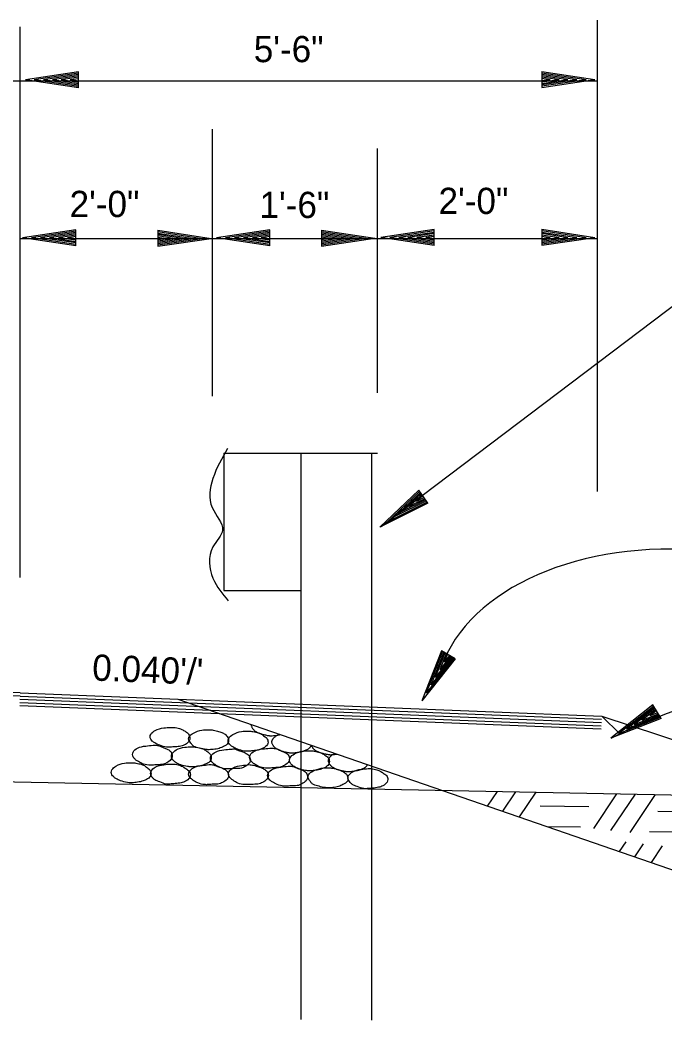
# Model space of a CAD drawing. Extents: x 1931522 to 1935523, y 600380 to 605075.
# Drawn here: x 1933348.9 to 1933498.3, y 604722.8 to 604954.5 of the extents above; entities that cross this region are included whole.
import ezdxf

# ---------------------------------------------------------------- set-up
doc = ezdxf.new("R2010")
doc.units = 0
doc.layers.add('Default', color=7, linetype='Continuous')
doc.layers.add('R_Border', color=7, linetype='Continuous')

msp = doc.modelspace()

# ---------------------------------------------------------------- linework, layer by layer
at = {"layer": 'Default'}
for p, q in [((1933482.65, 604845.22), (1933482.65, 604954.46)), ((1933348.95, 604825.33), (1933348.95, 604952.88)), ((1933152.12, 604940.38), (1933482.65, 604940.38)), ((1933362.48, 604942.45), (1933350.16, 604940.6)), ((1933362.48, 604938.73), (1933350.16, 604940.6)), ((1933362.48, 604942.13), (1933352.22, 604940.6)), ((1933362.48, 604939.05), (1933352.22, 604940.6)), ((1933362.48, 604941.81), (1933354.34, 604940.6)), ((1933362.48, 604939.37), (1933354.34, 604940.6)), ((1933362.48, 604941.51), (1933356.41, 604940.6)), ((1933362.48, 604939.67), (1933356.41, 604940.6)), ((1933362.48, 604941.19), (1933358.47, 604940.6)), ((1933362.48, 604939.99), (1933358.47, 604940.6)), ((1933362.48, 604940.87), (1933360.54, 604940.6)), ((1933362.48, 604940.31), (1933360.54, 604940.6)), ((1933362.48, 604938.73), (1933362.48, 604942.45)), ((1933469.71, 604942.57), (1933482.03, 604940.7)), ((1933469.71, 604942.57), (1933469.71, 604938.86)), ((1933469.71, 604942.25), (1933479.97, 604940.7)), ((1933469.71, 604941.93), (1933477.85, 604940.7)), ((1933469.71, 604941.64), (1933475.78, 604940.7)), ((1933469.71, 604941.32), (1933473.72, 604940.7)), ((1933469.71, 604941), (1933471.65, 604940.7)), ((1933469.71, 604938.86), (1933482.03, 604940.7)), ((1933469.71, 604940.11), (1933473.72, 604940.7)), ((1933469.71, 604939.5), (1933477.85, 604940.7)), ((1933469.71, 604939.18), (1933479.97, 604940.7)), ((1933469.71, 604939.79), (1933475.78, 604940.7)), ((1933469.71, 604940.43), (1933471.65, 604940.7)), ((1933393.51, 604867.32), (1933393.51, 604929.19)), ((1933431.72, 604868.12), (1933431.72, 604924.68)), ((1933361.82, 604905.89), (1933349.49, 604904.04)), ((1933361.82, 604905.57), (1933351.56, 604904.04)), ((1933361.82, 604902.17), (1933361.82, 604905.89)), ((1933380.84, 604905.76), (1933393.16, 604903.89)), ((1933380.84, 604905.76), (1933380.84, 604902.05)), ((1933406.72, 604905.89), (1933394.39, 604904.04)), ((1933406.72, 604905.57), (1933396.46, 604904.04)), ((1933406.72, 604902.17), (1933406.72, 604905.89)), ((1933418.7, 604905.79), (1933431.03, 604903.92)), ((1933418.7, 604905.79), (1933418.7, 604902.07)), ((1933444.81, 604905.91), (1933432.48, 604904.07)), ((1933444.81, 604905.59), (1933434.55, 604904.07)), ((1933444.81, 604902.2), (1933444.81, 604905.91)), ((1933469.71, 604905.99), (1933482.03, 604904.12)), ((1933469.71, 604905.99), (1933469.71, 604902.27)), ((1933469.71, 604905.67), (1933479.97, 604904.12)), ((1933348.95, 604903.82), (1933482.65, 604903.82)), ((1933361.82, 604902.17), (1933349.49, 604904.04)), ((1933361.82, 604902.49), (1933351.56, 604904.04)), ((1933361.82, 604905.25), (1933353.68, 604904.04)), ((1933361.82, 604902.81), (1933353.68, 604904.04)), ((1933361.82, 604904.95), (1933355.74, 604904.04)), ((1933361.82, 604903.11), (1933355.74, 604904.04)), ((1933361.82, 604904.63), (1933357.81, 604904.04)), ((1933361.82, 604903.43), (1933357.81, 604904.04)), ((1933361.82, 604904.31), (1933359.88, 604904.04)), ((1933361.82, 604903.75), (1933359.88, 604904.04)), ((1933380.84, 604905.44), (1933391.1, 604903.89)), ((1933380.84, 604905.12), (1933388.98, 604903.89)), ((1933380.84, 604904.83), (1933386.92, 604903.89)), ((1933380.84, 604904.51), (1933384.85, 604903.89)), ((1933380.84, 604904.19), (1933382.78, 604903.89)), ((1933380.84, 604902.05), (1933393.16, 604903.89)), ((1933380.84, 604903.3), (1933384.85, 604903.89)), ((1933380.84, 604902.69), (1933388.98, 604903.89)), ((1933380.84, 604902.37), (1933391.1, 604903.89)), ((1933380.84, 604902.98), (1933386.92, 604903.89)), ((1933380.84, 604903.62), (1933382.78, 604903.89)), ((1933406.72, 604902.17), (1933394.39, 604904.04)), ((1933406.72, 604902.49), (1933396.46, 604904.04)), ((1933406.72, 604905.25), (1933398.58, 604904.04)), ((1933406.72, 604902.81), (1933398.58, 604904.04)), ((1933406.72, 604904.95), (1933400.64, 604904.04)), ((1933406.72, 604903.11), (1933400.64, 604904.04)), ((1933406.72, 604904.63), (1933402.71, 604904.04)), ((1933406.72, 604903.43), (1933402.71, 604904.04)), ((1933406.72, 604904.31), (1933404.78, 604904.04)), ((1933406.72, 604903.75), (1933404.78, 604904.04)), ((1933418.7, 604905.47), (1933428.96, 604903.92)), ((1933418.7, 604905.15), (1933426.85, 604903.92)), ((1933418.7, 604904.85), (1933424.78, 604903.92)), ((1933418.7, 604904.53), (1933422.71, 604903.92)), ((1933418.7, 604904.21), (1933420.65, 604903.92)), ((1933418.7, 604902.07), (1933431.03, 604903.92)), ((1933418.7, 604903.33), (1933422.71, 604903.92)), ((1933418.7, 604902.71), (1933426.85, 604903.92)), ((1933418.7, 604902.39), (1933428.96, 604903.92)), ((1933418.7, 604903.01), (1933424.78, 604903.92)), ((1933418.7, 604903.65), (1933420.65, 604903.92)), ((1933444.81, 604902.2), (1933432.48, 604904.07)), ((1933444.81, 604902.52), (1933434.55, 604904.07)), ((1933444.81, 604905.27), (1933436.66, 604904.07)), ((1933444.81, 604902.84), (1933436.66, 604904.07)), ((1933444.81, 604904.98), (1933438.73, 604904.07)), ((1933444.81, 604903.13), (1933438.73, 604904.07)), ((1933444.81, 604904.66), (1933440.8, 604904.07)), ((1933444.81, 604903.45), (1933440.8, 604904.07)), ((1933444.81, 604904.34), (1933442.86, 604904.07)), ((1933444.81, 604903.77), (1933442.86, 604904.07)), ((1933469.71, 604905.35), (1933477.85, 604904.12)), ((1933469.71, 604905.05), (1933475.78, 604904.12)), ((1933469.71, 604904.73), (1933473.72, 604904.12)), ((1933469.71, 604904.41), (1933471.65, 604904.12)), ((1933469.71, 604902.27), (1933482.03, 604904.12)), ((1933469.71, 604903.52), (1933473.72, 604904.12)), ((1933469.71, 604902.91), (1933477.85, 604904.12)), ((1933469.71, 604902.59), (1933479.97, 604904.12)), ((1933469.71, 604903.2), (1933475.78, 604904.12)), ((1933469.71, 604903.84), (1933471.65, 604904.12)), ((1933432.53, 604837.14), (1933501.84, 604889.53)), ((1933396.07, 604854.15), (1933396.07, 604822.31)), ((1933396.07, 604854.15), (1933431.72, 604854.15)), ((1933413.91, 604854.15), (1933413.91, 604722.96)), ((1933430.29, 604854), (1933430.29, 604722.83)), ((1933441.27, 604845.56), (1933432.21, 604837)), ((1933441.47, 604845.32), (1933433.89, 604838.16)), ((1933443.36, 604842.56), (1933441.27, 604845.56)), ((1933441.67, 604845.03), (1933435.69, 604839.43)), ((1933443, 604843.06), (1933435.69, 604839.43)), ((1933441.79, 604844.77), (1933437.35, 604840.59)), ((1933442.82, 604843.32), (1933437.35, 604840.59)), ((1933441.98, 604844.56), (1933439.03, 604841.77)), ((1933442.63, 604843.59), (1933439.03, 604841.77)), ((1933442.15, 604844.29), (1933440.73, 604842.96)), ((1933442.5, 604843.87), (1933440.73, 604842.96)), ((1933443.36, 604842.56), (1933432.21, 604837)), ((1933443.22, 604842.79), (1933433.89, 604838.16)), ((1933396.07, 604822.31), (1933413.91, 604822.31)), ((1933446.51, 604808.38), (1933441.93, 604796.77)), ((1933449.7, 604806.51), (1933446.51, 604808.38)), ((1933449.7, 604806.51), (1933441.93, 604796.77)), ((1933446.75, 604808.19), (1933442.96, 604798.57)), ((1933449.46, 604806.68), (1933442.96, 604798.57)), ((1933447.05, 604808.04), (1933444.02, 604800.41)), ((1933449.14, 604806.81), (1933444.02, 604800.41)), ((1933447.29, 604807.89), (1933445.03, 604802.16)), ((1933448.89, 604806.98), (1933445.03, 604802.16)), ((1933447.59, 604807.74), (1933446.09, 604803.98)), ((1933448.62, 604807.13), (1933446.09, 604803.98)), ((1933447.88, 604807.57), (1933447.15, 604805.75)), ((1933448.35, 604807.3), (1933447.15, 604805.75)), ((1933348.95, 604798.61), (1933201.33, 604804.52)), ((1933348.95, 604797.88), (1933201.33, 604803.78)), ((1933348.89, 604797.14), (1933483.54, 604791.75)), ((1933348.91, 604797.88), (1933483.57, 604792.49)), ((1933348.95, 604798.61), (1933483.61, 604793.23)), ((1933385.48, 604797.15), (1933446.72, 604776.01)), ((1933348.83, 604795.66), (1933483.48, 604790.27)), ((1933348.85, 604796.4), (1933483.51, 604791.01)), ((1933495.47, 604795.86), (1933485.72, 604788.08)), ((1933495.64, 604795.56), (1933487.52, 604789.09)), ((1933495.79, 604795.29), (1933489.34, 604790.18)), ((1933495.93, 604795.05), (1933491.11, 604791.21)), ((1933496.08, 604794.75), (1933492.91, 604792.24)), ((1933496.25, 604794.48), (1933494.73, 604793.28)), ((1933497.34, 604792.64), (1933495.47, 604795.86)), ((1933483.61, 604793.23), (1933664.23, 604733.18)), ((1933483.61, 604793.23), (1933487.84, 604789.02)), ((1933497.34, 604792.64), (1933485.72, 604788.08)), ((1933497.16, 604792.91), (1933487.52, 604789.09)), ((1933496.99, 604793.18), (1933489.34, 604790.18)), ((1933496.84, 604793.42), (1933491.11, 604791.21)), ((1933496.7, 604793.69), (1933492.91, 604792.24)), ((1933496.55, 604793.99), (1933494.73, 604793.28)), ((1933147.68, 604781.96), (1933541.06, 604774.13)), ((1933446.72, 604776.01), (1933570.77, 604733.18))]:
    msp.add_line(p, q, dxfattribs=at)
msp.add_arc((1933541.23, 604679.75), 121.72, 64.8876, 117.1378, dxfattribs=at)
msp.add_ellipse((1933505.82, 604791.35), major_axis=(-60.8, 7.42), ratio=0.655798, start_param=4.712389, end_param=6.093533, dxfattribs=at)
for points in [[(1933396.93, 604855.18), (1933393.58, 604848.26), (1933393.41, 604841.52), (1933395.82, 604836.33), (1933393.58, 604832.4), (1933393.58, 604825.14), (1933397.13, 604819.9)], [(1933383.82, 604790.6), (1933382.19, 604790.5), (1933380.22, 604789.91), (1933379.19, 604788.98), (1933379.04, 604788.44), (1933379.53, 604787.45), (1933380.12, 604787.01), (1933381.26, 604786.47), (1933382.83, 604786.03), (1933383.67, 604786.03), (1933384.85, 604786.12), (1933386.18, 604786.27), (1933387.21, 604786.67), (1933388.1, 604787.5), (1933388.24, 604788.14), (1933387.95, 604789.03), (1933387.31, 604789.62), (1933386.62, 604790.01), (1933385.54, 604790.45), (1933384.85, 604790.6), (1933383.82, 604790.6)], [(1933392.63, 604790.08), (1933391.01, 604789.98), (1933389.09, 604789.29), (1933388.1, 604788.5), (1933387.96, 604787.96), (1933388.5, 604786.93), (1933388.94, 604786.39), (1933390.12, 604785.89), (1933391.6, 604785.55), (1933392.43, 604785.45), (1933393.66, 604785.5), (1933395.04, 604785.75), (1933396.03, 604786.19), (1933397.06, 604786.98), (1933397.21, 604787.62), (1933396.91, 604788.5), (1933396.17, 604789.14), (1933395.44, 604789.49), (1933394.35, 604789.83), (1933393.66, 604789.98), (1933392.63, 604790.08)], [(1933401.81, 604789.71), (1933400.18, 604789.66), (1933398.22, 604788.97), (1933397.23, 604788.08), (1933397.08, 604787.49), (1933397.63, 604786.51), (1933398.17, 604786.07), (1933399.25, 604785.57), (1933400.82, 604785.13), (1933401.66, 604785.08), (1933402.84, 604785.18), (1933404.17, 604785.43), (1933405.2, 604785.82), (1933406.19, 604786.61), (1933406.34, 604787.2), (1933406.04, 604788.08), (1933405.3, 604788.67), (1933404.61, 604789.17), (1933403.53, 604789.51), (1933402.84, 604789.66), (1933401.81, 604789.71)], [(1933402.43, 604791.3), (1933402.43, 604791.27), (1933402.42, 604791.2), (1933402.43, 604791.13), (1933402.51, 604790.87), (1933402.62, 604790.6), (1933402.78, 604790.35), (1933402.87, 604790.22), (1933402.97, 604790.1), (1933403.23, 604789.85), (1933403.52, 604789.66), (1933403.78, 604789.51), (1933404.05, 604789.38), (1933404.32, 604789.27), (1933404.6, 604789.17), (1933405.38, 604788.95), (1933406.17, 604788.77), (1933406.59, 604788.7), (1933406.8, 604788.68), (1933407.01, 604788.67), (1933407.6, 604788.7), (1933407.89, 604788.73), (1933408.19, 604788.77), (1933408.71, 604788.85), (1933409.23, 604788.95)], [(1933409.09, 604789), (1933408.79, 604788.88), (1933408.55, 604788.77), (1933408.31, 604788.65), (1933408.01, 604788.47), (1933407.76, 604788.25), (1933407.53, 604788), (1933407.43, 604787.86), (1933407.32, 604787.71), (1933407.25, 604787.58), (1933407.19, 604787.44), (1933407.17, 604787.31), (1933407.17, 604787.24), (1933407.17, 604787.17), (1933407.25, 604786.9), (1933407.36, 604786.64), (1933407.52, 604786.38), (1933407.61, 604786.26), (1933407.72, 604786.14), (1933407.97, 604785.89), (1933408.26, 604785.7), (1933408.52, 604785.55), (1933408.79, 604785.42), (1933409.06, 604785.3), (1933409.34, 604785.2), (1933410.12, 604784.98), (1933410.91, 604784.81), (1933411.75, 604784.71), (1933411.9, 604784.71), (1933412.05, 604784.72), (1933412.34, 604784.74), (1933412.93, 604784.81), (1933413.27, 604784.86), (1933413.6, 604784.92), (1933413.93, 604784.98), (1933414.26, 604785.06), (1933414.53, 604785.13), (1933414.78, 604785.22), (1933415.04, 604785.33), (1933415.29, 604785.45), (1933415.57, 604785.6), (1933415.83, 604785.77), (1933416.06, 604785.97), (1933416.17, 604786.1), (1933416.28, 604786.24), (1933416.35, 604786.36), (1933416.39, 604786.48)], [(1933379.74, 604786.49), (1933378.02, 604786.3), (1933376.1, 604785.8), (1933375.11, 604784.87), (1933374.97, 604784.33), (1933375.46, 604783.29), (1933376.05, 604782.85), (1933377.13, 604782.26), (1933378.71, 604781.87), (1933379.49, 604781.87), (1933380.72, 604781.97), (1933382.1, 604782.06), (1933383.13, 604782.56), (1933384.02, 604783.39), (1933384.17, 604784.03), (1933383.87, 604784.92), (1933383.13, 604785.51), (1933382.45, 604785.8), (1933381.36, 604786.25), (1933380.72, 604786.44), (1933379.74, 604786.49)], [(1933388.67, 604786.07), (1933387.05, 604786.03), (1933385.08, 604785.39), (1933384.09, 604784.45), (1933383.95, 604783.91), (1933384.49, 604782.88), (1933385.03, 604782.43), (1933386.11, 604781.94), (1933387.69, 604781.55), (1933388.52, 604781.45), (1933389.7, 604781.55), (1933391.03, 604781.79), (1933392.07, 604782.19), (1933393.05, 604782.97), (1933393.2, 604783.61), (1933392.9, 604784.5), (1933392.16, 604785.09), (1933391.48, 604785.53), (1933390.39, 604785.88), (1933389.7, 604786.03), (1933388.67, 604786.07)], [(1933397.77, 604785.57), (1933396.14, 604785.43), (1933394.17, 604784.89), (1933393.14, 604783.95), (1933392.99, 604783.41), (1933393.53, 604782.43), (1933394.07, 604781.98), (1933395.21, 604781.34), (1933396.73, 604781), (1933397.57, 604781), (1933398.75, 604781.1), (1933400.18, 604781.15), (1933401.16, 604781.64), (1933402.1, 604782.47), (1933402.24, 604783.11), (1933401.95, 604784), (1933401.26, 604784.59), (1933400.52, 604784.93), (1933399.49, 604785.28), (1933398.8, 604785.57), (1933397.77, 604785.57)], [(1933406.72, 604785.8), (1933405.1, 604785.61), (1933403.18, 604785.12), (1933402.19, 604784.18), (1933402.05, 604783.64), (1933402.59, 604782.61), (1933403.13, 604782.16), (1933404.21, 604781.57), (1933405.79, 604781.18), (1933406.57, 604781.18), (1933407.8, 604781.28), (1933409.13, 604781.38), (1933410.21, 604781.87), (1933411.15, 604782.7), (1933411.3, 604783.34), (1933411, 604784.23), (1933410.26, 604784.82), (1933409.53, 604785.12), (1933408.49, 604785.61), (1933407.75, 604785.75), (1933406.72, 604785.8)], [(1933416.02, 604785.16), (1933414.4, 604785.12), (1933412.43, 604784.48), (1933411.45, 604783.54), (1933411.3, 604783), (1933411.84, 604781.97), (1933412.38, 604781.52), (1933413.46, 604781.03), (1933415.04, 604780.64), (1933415.87, 604780.54), (1933417.05, 604780.64), (1933418.38, 604780.88), (1933419.42, 604781.28), (1933420.4, 604782.06), (1933420.55, 604782.7), (1933420.25, 604783.59), (1933419.52, 604784.18), (1933418.83, 604784.62), (1933417.74, 604784.97), (1933417.05, 604785.12), (1933416.02, 604785.16)], [(1933416.34, 604786.5), (1933416.43, 604786.29), (1933416.53, 604786.09), (1933416.67, 604785.9), (1933416.82, 604785.71), (1933417.07, 604785.46), (1933417.36, 604785.27), (1933417.62, 604785.13), (1933417.89, 604784.99), (1933418.16, 604784.88), (1933418.44, 604784.78), (1933419.22, 604784.56), (1933420.02, 604784.38), (1933420.43, 604784.32), (1933420.64, 604784.29), (1933420.85, 604784.29), (1933421.44, 604784.31), (1933422.03, 604784.38), (1933422.34, 604784.43)], [(1933421.92, 604784.57), (1933421.66, 604784.45), (1933421.52, 604784.39), (1933421.39, 604784.32), (1933421.1, 604784.14), (1933420.85, 604783.92), (1933420.62, 604783.67), (1933420.51, 604783.53), (1933420.41, 604783.38), (1933420.33, 604783.25), (1933420.28, 604783.11), (1933420.25, 604782.98), (1933420.25, 604782.91), (1933420.26, 604782.84), (1933420.33, 604782.57), (1933420.45, 604782.31), (1933420.61, 604782.05), (1933420.7, 604781.93), (1933420.8, 604781.81), (1933421.06, 604781.56), (1933421.34, 604781.37), (1933421.61, 604781.22), (1933421.87, 604781.09), (1933422.15, 604780.97), (1933422.43, 604780.87), (1933423.21, 604780.65), (1933424, 604780.48), (1933424.84, 604780.38), (1933424.98, 604780.38), (1933425.13, 604780.39), (1933425.43, 604780.41), (1933426.02, 604780.48), (1933426.35, 604780.53), (1933426.69, 604780.59), (1933427.02, 604780.65), (1933427.35, 604780.73), (1933427.61, 604780.8), (1933427.87, 604780.89), (1933428.13, 604781), (1933428.38, 604781.12), (1933428.66, 604781.27), (1933428.91, 604781.43), (1933429.15, 604781.64), (1933429.26, 604781.77), (1933429.31, 604781.83), (1933429.36, 604781.91), (1933429.41, 604781.99)], [(1933374.72, 604782.4), (1933373.1, 604782.35), (1933371.13, 604781.66), (1933370.19, 604780.78), (1933370.05, 604780.19), (1933370.54, 604779.2), (1933371.13, 604778.76), (1933372.16, 604778.27), (1933373.78, 604777.82), (1933374.57, 604777.78), (1933375.8, 604777.87), (1933377.13, 604778.12), (1933378.16, 604778.51), (1933379.1, 604779.3), (1933379.25, 604779.89), (1933378.95, 604780.78), (1933378.21, 604781.37), (1933377.52, 604781.86), (1933376.44, 604782.2), (1933375.75, 604782.35), (1933374.72, 604782.4)], [(1933383.82, 604782.11), (1933382.2, 604781.97), (1933380.23, 604781.38), (1933379.3, 604780.49), (1933379.15, 604779.9), (1933379.64, 604778.92), (1933380.13, 604778.47), (1933381.26, 604777.98), (1933382.79, 604777.49), (1933383.63, 604777.49), (1933384.86, 604777.59), (1933386.23, 604777.78), (1933387.22, 604778.13), (1933388.2, 604779.01), (1933388.35, 604779.6), (1933388.06, 604780.49), (1933387.32, 604781.08), (1933386.58, 604781.52), (1933385.55, 604781.92), (1933384.86, 604782.06), (1933383.82, 604782.11)], [(1933392.67, 604781.98), (1933391.05, 604781.79), (1933389.08, 604781.24), (1933388.1, 604780.36), (1933387.95, 604779.77), (1933388.49, 604778.78), (1933389.03, 604778.34), (1933390.11, 604777.75), (1933391.64, 604777.36), (1933392.48, 604777.36), (1933393.71, 604777.46), (1933395.03, 604777.55), (1933396.07, 604778), (1933397.05, 604778.88), (1933397.2, 604779.47), (1933396.9, 604780.36), (1933396.17, 604780.95), (1933395.43, 604781.29), (1933394.35, 604781.69), (1933393.71, 604781.93), (1933392.67, 604781.98)], [(1933401.93, 604781.99), (1933400.26, 604781.79), (1933398.29, 604781.25), (1933397.31, 604780.37), (1933397.16, 604779.78), (1933397.7, 604778.79), (1933398.24, 604778.35), (1933399.37, 604777.71), (1933400.9, 604777.36), (1933401.69, 604777.36), (1933402.92, 604777.41), (1933404.29, 604777.56), (1933405.33, 604778), (1933406.26, 604778.89), (1933406.41, 604779.48), (1933406.11, 604780.37), (1933405.38, 604780.96), (1933404.64, 604781.3), (1933403.6, 604781.65), (1933402.97, 604781.84), (1933401.93, 604781.99)], [(1933411, 604781.62), (1933409.28, 604781.42), (1933407.41, 604780.93), (1933406.38, 604780), (1933406.23, 604779.46), (1933406.77, 604778.42), (1933407.31, 604777.98), (1933408.44, 604777.39), (1933409.97, 604777), (1933410.76, 604777), (1933411.99, 604777.09), (1933413.41, 604777.19), (1933414.4, 604777.68), (1933415.33, 604778.52), (1933415.48, 604779.16), (1933415.18, 604780.05), (1933414.45, 604780.64), (1933413.76, 604780.93), (1933412.68, 604781.33), (1933412.04, 604781.57), (1933411, 604781.62)], [(1933420.28, 604781.24), (1933418.65, 604781.15), (1933416.73, 604780.46), (1933415.75, 604779.67), (1933415.6, 604779.13), (1933416.14, 604778.09), (1933416.59, 604777.55), (1933417.77, 604777.06), (1933419.24, 604776.72), (1933420.08, 604776.62), (1933421.31, 604776.67), (1933422.69, 604776.91), (1933423.67, 604777.36), (1933424.71, 604778.14), (1933424.85, 604778.78), (1933424.56, 604779.67), (1933423.82, 604780.31), (1933423.08, 604780.65), (1933422, 604781), (1933421.31, 604781.15), (1933420.28, 604781.24)], [(1933429.53, 604781.06), (1933427.91, 604780.91), (1933425.94, 604780.32), (1933425, 604779.43), (1933424.85, 604778.84), (1933425.35, 604777.86), (1933425.84, 604777.41), (1933426.97, 604776.92), (1933428.5, 604776.43), (1933429.33, 604776.43), (1933430.56, 604776.53), (1933431.94, 604776.73), (1933432.92, 604777.07), (1933433.91, 604777.96), (1933434.06, 604778.55), (1933433.76, 604779.43), (1933433.02, 604780.02), (1933432.28, 604780.47), (1933431.25, 604780.86), (1933430.56, 604781.01), (1933429.53, 604781.06)]]:
    msp.add_spline(points, degree=3, dxfattribs=at)
at = {"layer": 'R_Border'}
for p, q in [((1933457.18, 604772.4), (1933459.45, 604775.76)), ((1933460.67, 604771.19), (1933463.69, 604775.67)), ((1933464.53, 604769.86), (1933468.39, 604775.58)), ((1933481.76, 604767.22), (1933487.14, 604775.21)), ((1933485.74, 604766.76), (1933491.39, 604775.12)), ((1933490.19, 604766.29), (1933496.08, 604775.03)), ((1933469.33, 604772.41), (1933480.64, 604772.32)), ((1933496.59, 604771.21), (1933507.9, 604771.12)), ((1933470.92, 604767.66), (1933478.7, 604767.59)), ((1933494.64, 604766.48), (1933505.95, 604766.39)), ((1933487.75, 604761.84), (1933489.26, 604764.09)), ((1933491.24, 604760.64), (1933493.25, 604763.62)), ((1933495.1, 604759.31), (1933497.7, 604763.16))]:
    msp.add_line(p, q, dxfattribs=at)

# ---------------------------------------------------------------- texts
at = {"layer": 'Default'}
for s, rotation, p in [('5\'-6"', 360, (1933403.03, 604944.69)), ('2\'-0"', 360, (1933360.39, 604908.82)), ('2\'-0"', 360, (1933445.82, 604909.53)), ('1\'-6"', 360, (1933404.36, 604908.6)), ("0.040'/'", 357.7094, (1933365.53, 604801.48))]:
    msp.add_text(s, height=6.075, rotation=rotation, dxfattribs=at).set_placement(p)

doc.saveas('drawing.dxf')
